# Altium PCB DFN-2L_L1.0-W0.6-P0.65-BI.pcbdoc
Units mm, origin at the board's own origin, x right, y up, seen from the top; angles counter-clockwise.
Board outline 14.1 x 13.6 mm, 2 copper layers (Top Layer, Bottom Layer), stack 0 mm thick; 1 components, 0 nets, 2 pads, 0 vias.
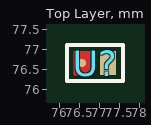
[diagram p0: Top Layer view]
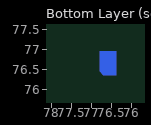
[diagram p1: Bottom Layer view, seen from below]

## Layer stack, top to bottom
Top Layer: signal copper (thickness not stored)
Bottom Layer: signal copper (thickness not stored)

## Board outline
83.95,69.85 69.85,69.85 69.85,83.45 83.95,83.45

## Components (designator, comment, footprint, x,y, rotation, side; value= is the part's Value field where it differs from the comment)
U? "" DFN-2L_L1.0-W0.6-P0.65-BI 76.9,76.65 r0 top

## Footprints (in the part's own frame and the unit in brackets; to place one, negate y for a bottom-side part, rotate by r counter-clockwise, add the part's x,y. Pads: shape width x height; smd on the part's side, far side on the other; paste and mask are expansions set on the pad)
DFN-2L_L1.0-W0.6-P0.65-BI [mm]
  round 0.202 smd: 1(-0.328,0.004)
  rect 0.4x0.6 smd: 2(0.325,0)
  Top Layer region: -0.53,0.3 -0.53,-0.3 -0.2,-0.3 -0.12,-0.2 -0.12,0.3
  Bottom Layer region: -0.53,0.3 -0.53,-0.3 -0.2,-0.3 -0.12,-0.2 -0.12,0.3
  Multi-Layer region: -0.53,0.3 -0.53,-0.3 -0.2,-0.3 -0.12,-0.2 -0.12,0.3
  silkscreen extent -0.7,-0.45 0.7,0.45

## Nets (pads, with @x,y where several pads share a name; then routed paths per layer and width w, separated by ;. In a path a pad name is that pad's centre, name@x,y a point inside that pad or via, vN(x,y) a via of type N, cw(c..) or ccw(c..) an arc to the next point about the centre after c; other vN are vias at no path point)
pads on no net: U?.1 U?.2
